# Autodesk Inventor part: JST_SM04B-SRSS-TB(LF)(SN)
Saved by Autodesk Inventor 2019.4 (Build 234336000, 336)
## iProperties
Created: 2021-02
Part Number: JST_SM04B-SRSS-TB(LF)(SN)
Material: Generic
Document SubType Name: Modeling
Designer: Administrator
Density: 1 g/cm^3
Appearance: Default
Title: JST_SM04B-SRSS-TB(LF)(SN)
Author: Administrator
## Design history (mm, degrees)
feature "Body1"
body "Solid1"
